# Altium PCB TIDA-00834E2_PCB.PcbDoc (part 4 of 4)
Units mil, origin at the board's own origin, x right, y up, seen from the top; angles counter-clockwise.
Board outline 7480.31 x 4133.86 mil, 4 copper layers (Top Layer, GND, PWR, Bottom Layer), stack 61.912 mil thick; 550 components, 248 nets, 1167 pads, 312 vias.
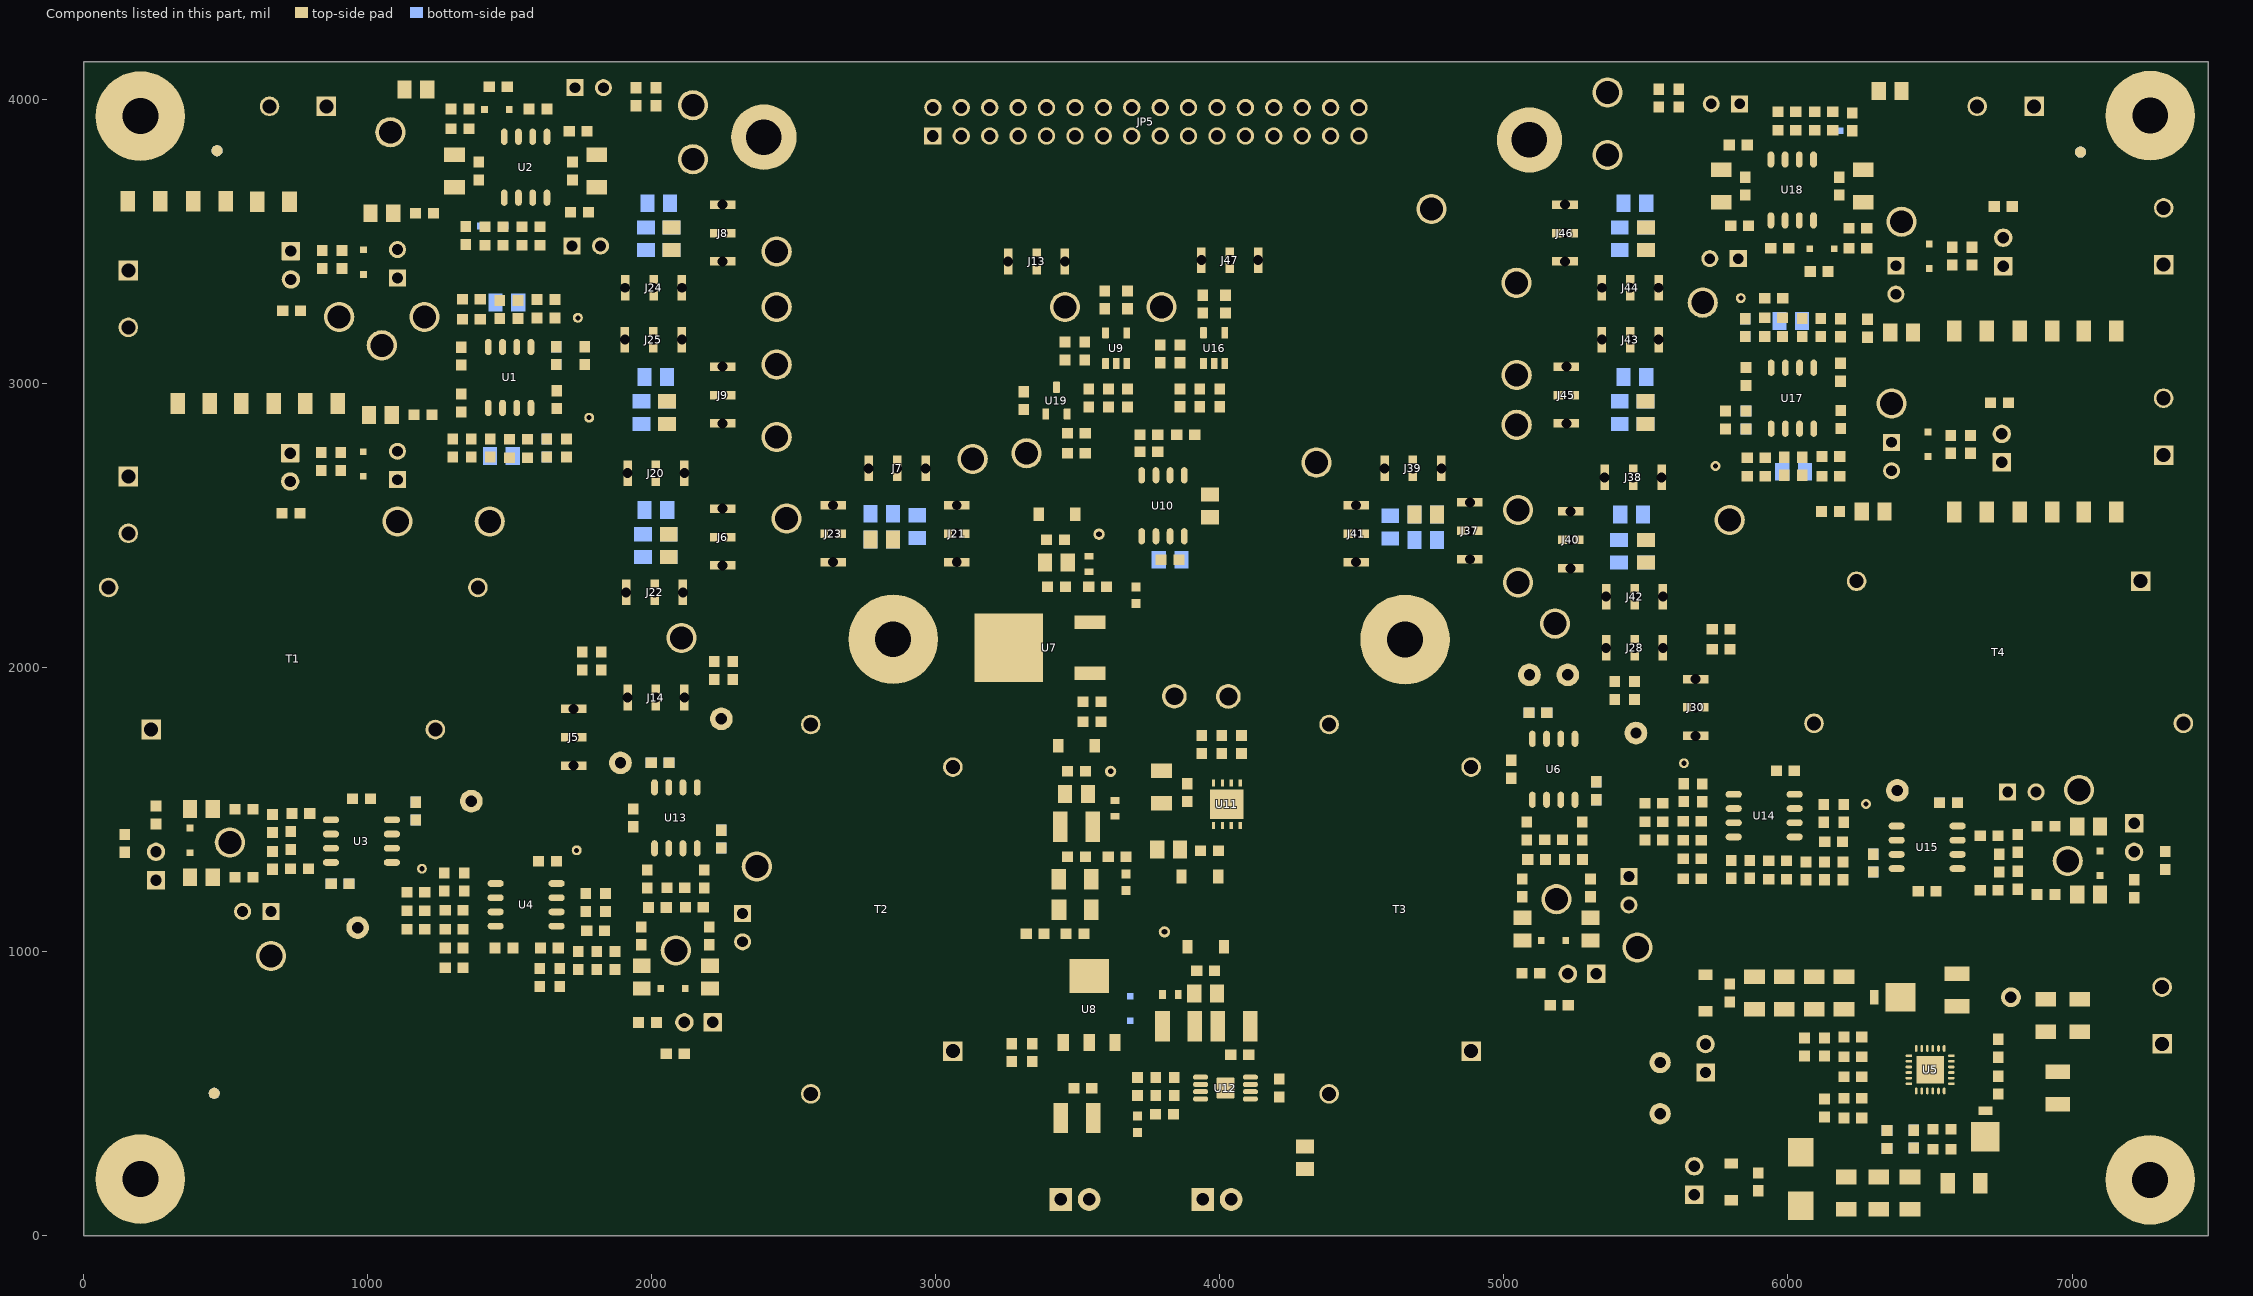
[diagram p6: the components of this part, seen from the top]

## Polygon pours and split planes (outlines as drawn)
GND1 on Top Layer "GND1_L01_P068" (solid, remove dead copper, pour order 68): 5750,135 5760,145 5825,145 5845,145 5855,155 5855,165 5865,175 5935,175 5975,175 5995,155 6065,155 6115,155 6130,140 6155,115 6180,115 6580,115 6590,105 6590,75 6590,55 6565,30 6430,30 5775,30 5750,55
NetC25_1 on Top Layer "Top Layer-No Net" (solid, remove dead copper, pour order 32): 5585,295 5585,240 5615,210 5680,210 5715,210 5745,240 5805,240 5845,240 5855,230 5855,225 5855,210 5860,205 5865,200 5890,200 5925,200 5935,210 5935,235 5945,245 6100,245 6120,245 6135,230 6135,215 6135,190 6145,180 6195,180 6495,180 6505,170 6505,145 6512.64,137.36 6582.36,137.36 6590,145 6590,240 6580,250 6540,250 6530,260 6530,320 6525,325 6430,325 6425,320 6425,260 6415,250 6225,250 6210,265 6210,305 6210,335 6195,350 6193.86,351.14 6116.85,351.14 5616.14,351.14 5585,320
NetD4_2 on Top Layer "Top Layer-No Net" (solid, remove dead copper, pour order 26): 6540,511 6540,450 6555,435 6625,435 6630,435 6635,430 6640,425 6670,425 6770,425 6795,400 6795,345 6805,335 7035,335 7045,345 7045,465 7045,475 7035,485 7030,490 6910,490 6820,490 6790,460 6685,460 6680,460 6655,485 6655,520 6655,525 6645,535 6640,540 6590,540 6569,540
GND1 on Top Layer "Top Layer-No Net" (solid, remove dead copper, pour order 16): 5635,925 5635,909 5644,900 5737,900 5740,900 5770,870 5814,870 5825,870 5840,885 5843,888 6117,888 6228,888 6235,895 6235,975 6230,980 5648,980 5635,967 5635,926
NetD7_1 on Top Layer "Top Layer-No Net" (solid, remove dead copper, pour order 18): 6345,975 6345,775 6390,730 6390,625 6405,610 6435,610 6440,615 6440,645 6430,655 6430,725 6475,770 6675,770 6695,790 6695,815 6675,835 6495,835 6480,850 6480,975 6475,980 6350,980
NetD4_1 on Top Layer "Top Layer-No Net" (solid, remove dead copper, pour order 24): 6640,400 6625,385 6625,265 6650,240 6650,115 6660,105 6755,105 6765,115 6765,390 6755,400
+5V_IN on Top Layer "Top Layer-No Net" (solid, remove dead copper, pour order 6): 6565,610 6565,685 6600,720 6785,720 6810,745 7395,745 7410,730 7410,570 7390,550 6805,550 6790,565 6790,665 6780,675 6625,675 6615,665 6615,610
GND1 on Top Layer "Top Layer-No Net" (solid, remove dead copper, pour order 28): 6805,895 6550,895 6530,915 6530,965 6545,980 7380,980 7410,950 7410,830 7390,810 6890,810 6885,810 6870,825 6870,875 6850,895
NetC35_1 on Top Layer "Top Layer-No Net" (solid, remove dead copper, pour order 20): 5635,800 5645,810 5750,810 5760,820 5760,835 5770,845 5830,845 5850,825 6240,825 6260,845 6260,975 6265,980 6315,980 6320,975 6320,765 6370,715 6370,625 6370,605 6360,595 6325,595 6305,615 6305,725 6275,755 6090,755 6080,745 6080,690 6070,680 5995,680 5985,690 5985,745 5975,755 5795,755 5775,735 5775,650 5765,640 5645,640 5635,650
AGND on Top Layer "Top Layer-No Net" (solid, remove dead copper, pour order 34): 3817.28,441.64 3822.28,446.64 3982.24,446.64 3990,454.4 3990,590 3978.36,601.64 3897.28,601.64 3887.28,611.64 3887.28,780.9 3898.02,791.64 3957.28,791.64 3962.28,796.64 3962.28,961.64 3997.28,996.64 3997.28,1091.64 4007.28,1101.64 4068.36,1101.64 4080,1090 4080,855 4022.28,797.28 4022.28,686.64 4050,658.92 4050,394.36 4037.28,381.64 3828.36,381.64 3817.28,392.72
-12V on Top Layer "Top Layer-No Net" (solid, remove dead copper, pour order 36): 3882,883 3780,985 3780,1095 3790,1105 3885,1105 3895,1105 3905,1095 3905,1065 3905,985 3935,955 3935,920 3935,830 3925,820 3891,820 3882,829
-14V on Top Layer "Top Layer-No Net" (solid, remove dead copper, pour order 38): 4080,795 4090,805 4175,805 4185,795 4185,620 4170,605 4095,605 4080,620
+14V on Top Layer "Top Layer-No Net" (solid, remove dead copper, pour order 40): 3527.91,545 3537.91,555 3620,555 3630,545 3630,325 3620,315 3540,315 3527.91,327.09
AGND on Top Layer "Top Layer-No Net" (solid, remove dead copper, pour order 42): 3250,535 3250,620 3260,630 3360,630 3368.54,621.46 3368.54,556.46 3390,535 3467.91,535 3497.91,535 3502.91,530 3502.91,505 3502.91,485 3492.91,475 3462.91,445 3462.91,420 3462.91,355 3452.91,345 3397.91,345 3260,345 3250,355 3250,525
AGND on Top Layer "Top Layer-No Net" (solid, remove dead copper, pour order 44): 3325,1750 3435,1750 3450.53,1734.47 3450.53,1675 3455.53,1670 3479.07,1670 3485.53,1663.54 3485.53,1513.15 3465.53,1493.15 3465.53,1380 3485.53,1360 3485.53,1325 3475.53,1315 3322.62,1315 3312.62,1325 3312.62,1737.62
NetC54_1 on Top Layer "Top Layer-No Net" (solid, remove dead copper, pour order 46): 3615,850 3480,850 3470,860 3470,980 3505.53,1015.53 3505.53,1375 3525.53,1395 3525.53,1470 3525.53,1483.15 3535.53,1493.15 3562.46,1493.15 3592.38,1493.15 3600.53,1485 3600.53,1465 3600.53,1390 3620.53,1370 3625.53,1365 3625.53,1310 3625.53,860.53
NetC54_2 on Top Layer "Top Layer-No Net" (solid, remove dead copper, pour order 48): 3459.53,1291 3475.53,1275 3475.53,1110 3480.53,1105 3480.53,1032.53 3473,1025 3364,1025 3355.53,1033.47 3355.53,1275 3371.53,1291
+12V on Top Layer "Top Layer-No Net" (solid, remove dead copper, pour order 50): 3542.62,1750 3650,1750 3657.62,1742.38 3657.62,1600 3647.62,1590 3600.53,1590 3590.53,1580 3590.53,1570 3590.53,1530 3580.53,1520 3550.53,1520 3520.53,1520 3510.53,1530 3510.53,1660 3510.53,1665 3540.53,1695 3540.53,1747.91
AGND on Top Layer "Top Layer-No Net" (solid, remove dead copper, pour order 54): 3375,2605 3375,2500 3385,2490 3410,2490 3415,2485 3415,2210 3375,2170 3375,1950 3140,1950 3140,2210 3250,2320 3250,2605 3260,2615 3365,2615
+3.3V on Top Layer "Top Layer-No Net" (solid, remove dead copper, pour order 56): 3535,2605 3535,2510 3490,2465 3490,2340 3485,2335 3440,2335 3435,2340 3435,2495 3475,2535 3475,2605 3485,2615 3525,2615
AGND on Top Layer "Top Layer-No Net" (solid, remove dead copper, pour order 58): 3755,1545 3930,1545 3955,1570 4104.65,1570 4115,1559.65 4115,1480.35 4104.65,1470 3925,1470 3895,1440 3820,1440 3805,1425 3805,1305 3790,1290 3755,1290 3740,1305 3740,1530
NetC49_1 on Top Layer "NETC49_1_L01_P076" (solid, remove dead copper, pour order 76): 3525,2345 3525,2320 3525,2315 3520,2310 3515,2305 3460,2305 3445,2305 3440,2300 3440,2270 3440,2160 3465,2135 3540,2135 3585,2135 3610,2160 3610,2195 3575,2230 3560,2245 3555,2250 3555,2320 3555,2345 3550,2350 3530,2350
AGND on GND "AGND_L02_P066" (solid, remove dead copper, pour order 66): 50,3700 75,3725 225,3725 400,3725 425,3750 425,3950 425,4075 450,4100 1125,4100 1150,4075 1150,3400 1194,3356 1836,3356 1950,3470 1950,3475 1950,3775 2000,3825 2100,3925 2100,3975 2100,4075 2125,4100 2250,4100 5400,4100 5425,4075 5425,3900 5500,3825 5575,3750 5575,3725 5575,3475 5700,3350 6300,3350 6375,3425 6375,3550 6375,4075 6400,4100 7025,4100 7050,4075 7050,4025 7050,3750 7075,3725 7150,3725 7400,3725 7425,3700 7425,1025 7400,1000 7175,1000 5605,1000 5525,920 5525,775 5425,675 5150,400 5025,275 3375,275 3350,250 3350,75 3325,50 550,50 450,50 425,75 425,250 425,375 400,400 75,400 50,425
GND2 on GND "GND2_L02_P064" (solid, remove dead copper, pour order 64): 6350,4090 6325,4115 6075,4115 5480,4115 5470,4115 5450,4095 5450,4055 5450,3935 5600,3785 5600,3595 5600,3495 5720,3375 6275,3375 6350,3450
GND on GND "GND_L02_P062" (solid, remove dead copper, pour order 62): 1185,4085 1200,4100 1450,4100 2045,4100 2055,4100 2075,4080 2075,4040 2075,3935 1925,3785 1925,3580 1925,3505 1805,3385 1220,3385 1185,3420
GND1 on GND "GND1_L02_P060" (solid, remove dead copper, pour order 60): 7405,980 5635,980 5550,895 5550,850 5550,750 5050,250 3405.75,250 3375,219.25 3375,75 3420,30 5015,30 7030,30 7050,50 7050,140 7050,400 7075,425 7405,425 7410,425 7435,450 7435,910 7435,950
-12V on Bottom Layer "-12V_L04_P074" (solid, remove dead copper, pour order 74): 5285,1550 5290,1555 5345,1555 5365,1555 5405,1595 5415,1605 5435,1605 5515,1605 5715,1405 5815,1305 5815,1195 5815,1185 5830,1170 5835,1165 5880,1165 5940,1225 6135,1420 6280,1420 6520,1420 6575,1475 6580,1480 6580,1535 6580,1580 6590,1590 6870,1590 6940,1520 6940,115 6900,75 5935,75 5730,280 3420,280 3215,75 845,75 775,145 775,1140 850,1215 850,1230 850,1250 855,1255 885,1255 890,1250 890,1215 905,1200 905,1045 925,1025 1075,1025 1175,1025 1450,1300 1450,2090 1660,2300 1705,2300 1725,2280 1725,2235 1725,2070 1660,2005 1660,1145 1545,1030 1545,905 1555,895 1614.28,895 1699.74,980.46 1699.74,1139.74 1760,1200 1945,1200 1957.74,1212.74 2130,1385 2285,1385 2300,1370 2300,1205 2260,1165 2260,945 2195,880 2075,760 2075,510 2135,450 2260,450 3245,1435 3910,1435 4765,580 5305,580 5450,725 5450,890 5495,935 5495,1515 5460,1550 5445,1550 5410,1515 5360,1515 5290,1515 5285,1520
+12V on PWR "+12V_L03_P070" (solid, remove dead copper, pour order 70): 100,3650 125,3675 450,3675 475,3700 475,4025 500,4050 1050,4050 1075,4075 1575,4075 1600,4075 1625,4050 1625,4025 1625,3975 1650,3950 1875,3950 2100,3950 2125,3975 2125,4000 2150,4025 2275,4025 5425,4025 5475,4075 5800,4075 6450,4075 6500,4025 6750,4025 6975,4025 7000,4000 7000,3950 7000,3700 7025,3675 7100,3675 7350,3675 7375,3650 7375,3025 7375,1075 7350,1050 5575,1050 5475,950 5475,800 5000,325 3350,325 3300,275 3300,125 3275,100 525,100 500,125 500,325 500,450 475,475 325,475 125,475 100,500

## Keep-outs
Keep-Out Layer:
  lines w10: 25,375 400,375 400,0 ; 25,3741.85 400,3741.85 400,4107.01 ; 7075,21.85 7075,396.85 7450,396.85 ; 7075,4108.86 7075,3743.7 7450,3743.7 ; 25,25 25,4108.86 7455.31,4108.86 7455.31,25 25,25
  text ".Layer_Name" at 577,-858.49 h60

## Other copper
Top Layer:
  region net +5V_IN: 6465,705 6465,650 6470,645 6530,645 6535,650 6535,705 6530,710 6470,710
  text ".Layer_Name" at 577,-858.49 h60
GND:
  pour cut-out: 2250,4000 2250,3725 2550,3725 2550,4000
  pour cut-out: 4940,3995 4940,3720 5240,3720 5240,3995
  pour cut-out: 2655,2290 2655,1915 3055,1915 3055,2290
  pour cut-out: 4457,2289 4457,1914 4857,1914 4857,2289
  text ".Layer_Name" at 577,-858.49 h60
PWR:
  pour cut-out: 4940,2435 4940,2381.77 4940.08,2381.7 4938.38,2380 4840,2380 4840,2435
  pour cut-out: 5850,115 5850,40 5975,40 5975,70 5975,100 5930,115
  pour cut-out: 2250,4000 2250,3725 2550,3725 2550,4000
  pour cut-out: 4940,3995 4940,3720 5240,3720 5240,3995
  pour cut-out: 2655,2290 2655,1915 3055,1915 3055,2290
  pour cut-out: 4457,2289 4457,1914 4857,1914 4857,2289
  text ".Layer_Name" at 577,-858.49 h60
Bottom Layer:
  pour cut-out: 3657,873.5 3656.51,873.01 3656.51,717.51 3717,717.51 3717,873.5
  text ".Layer_Name" at 577,-858.49 h60

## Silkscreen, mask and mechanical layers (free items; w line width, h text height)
Top Overlay:
  circle w10: c3448,609 r9
  circle w6: c3885,575 r5.66
  circle w6: c3719.34,2415 r5.66
  circle w6: c3919.34,3035 r5.66
  circle w6: c6609.34,530 r5.66
  circle w6: c6609.34,1250 r5.66
  circle w6: c5759.34,1570 r5.66
  circle w6: c5059.34,1520 r5.66
  circle w6: c5934.34,2795 r5.66
  circle w6: c5924.34,3530 r5.66
  circle w6: c1964.34,1355 r5.66
  circle w6: c1405.42,1252.32 r5.66
  circle w6: c859.34,1510 r5.66
  circle w6: c1574.34,3180 r5.66
  circle w6: c1639.34,3915 r5.66
  circle w6: c3594.34,3030 r5.66
  circle w20: c2365,3629 r22
  circle w20: c2206,3334 r22
  circle w20: c2205,3195 r22
  circle w20: c2286,3157 r22
  circle w20: c2210,2683 r22
  circle w20: c2291,2656 r22
  circle w20: c2212,2254 r22
  circle w20: c1610,1857 r22
  circle w20: c2114,1800 r22
  circle w20: c2642,2679 r22
  circle w20: c2963,2826 r22
  circle w20: c3190,2573 r22
  circle w20: c3457,3536 r22
  circle w20: c3934,3535 r22
  circle w20: c4363,2571 r22
  circle w20: c4877,2273 r22
  circle w20: c4783,2810 r22
  circle w20: c5256,2700 r22
  circle w20: c5205,2637 r22
  circle w20: c5187,3150 r22
  circle w20: c5258,3199 r22
  circle w20: c5258,3321 r22
  circle w20: c5096,3632 r22
  circle w20: c5258,2244 r22
  circle w20: c5257,2070 r22
  circle w20: c5785,1961 r22
  lines w6: 497,1451 497,1556 ; 1245,640 1245,888 ; 1300,3415 1300,3342 ; 1560,670 1560,820 ; 1866,1360 1866,1253 ; 2060,816 2080,816 2084,820 2084,833 ; 2219,1156 2228,1156 2260,1188 ; 2297,961 2252,1006 2238,1006 ; 3564,2868 3545,2868 3540,2873 3540,2888 ; 3957.27,2890.02 3957.27,2888.73 3971,2875 4004,2875 4016,2863 ; 4075,3210 4154,3210 ; 5580,1040 5580,1218 ; 5755,2793 5762,2800 5762,2785 5754,2793 5825,2793 5834,2802 ; 5868,3329 5875,3322 5860,3322 5868,3330 5868,3282 5884,3266 ; 5899,1123 5899,1206 ; 6306.11,3573.88 6306.11,3575.11 6325,3594 6325,3620 6345,3640 6345,3659 ; 6940,1480 6940,1621 ; 1245,888 1239,882 1251,882 1245,888 ; 1300,3342 1293,3349 1306,3349 1306,3348 1300,3342 ; 1560,820 1553,813 1567,813 1560,820 ; 1866,1253 1860,1259 1871,1259 1871,1258 1866,1253 ; 2084,833 2079,828 2089,828 2084,833 ; 2238,1006 2244,1012 2244,1000 2238,1006 ; 2260,1188 2251,1188 2260,1179 2260,1188 ; 3540,2888 3533,2881 3546,2881 3546,2882 3540,2888 ; 5580,1218 5574,1212 5586,1212 5580,1218 ; 5899,1206 5893,1200 5904,1200 5904,1201 5899,1206 ; 6940,1621 6934,1615 6946,1615 6940,1621 ; 3395,635 3395,885 3455,885 3455,990 3625,990 3625,885 3685,885 3685,635 3395,635 ; 4074.5,3209.5 4082,3217 4082,3202 4074.5,3209.5
  text "2" at 2971,4045 h60
  text "14" at 3546,4045 h60
  text "20" at 3846,4045 h60
  text "8" at 3266,4040 h60
  text "26" at 4141,4040 h60
  text "32" at 4436,4040 h60
  text "19" at 3838.4,3750 h60
  text "7" at 3281,3745 h60
  text "13" at 3556,3745 h60
  text "25" at 4146,3745 h60
  text "31" at 4441,3745 h60
  text "1" at 2976,3740 h60
  text "FID1" at 435,415 h30
  text "'.PRJ_Number'.PCB_Rev" at 1694,149 h108.27
  text ".Layer_Name" at 577,-858.49 h60
Bottom Overlay:
  text "2" at 2991,4045 h60
  text "14" at 3636,4045 h60
  text "20" at 3946,4045 h60
  text "8" at 3326,4040 h60
  text "26" at 4241,4040 h60
  text "32" at 4536,4040 h60
  text "19" at 3931,3755 h60
  text "7" at 3301,3745 h60
  text "13" at 3656,3745 h60
  text "25" at 4241,3745 h60
  text "31" at 4521,3745 h60
  text "1" at 2996,3740 h60
  text "FID2" at 415,3695 h72.83
  text "FID3" at 6970,3665 h72.83
  text ".Layer_Name" at 577,-858.49 h60
Top Paste:
  text ".Layer_Name" at 577,-858.49 h60
Bottom Paste:
  text ".Layer_Name" at 577,-858.49 h60
Top Solder:
  text ".Layer_Name" at 577,-858.49 h60
  text ".Layer_Name" at 577,-858.49 h60
Bottom Solder:
  text ".Layer_Name" at 577,-858.49 h60
Drill Guide:
  text ".Layer_Name" at 577,-858.49 h60
M1 Board Outline:
  the board outline again, w10
M2 Board Dimensions:
  rectangle: 0,-275 125,-150
  rectangle: 125,-400 500,-275
  lines w7: 0,-275 1000,-275 ; 125,-400 125,-150 ; 250,-400 250,-150 ; 500,-400 500,-150 ; 750,-400 750,-150 ; 0,-400 1000,-400 1000,-150 0,-150 0,-400
M3 3D STEP Top:
  text ".Layer_Name" at 577,-858.49 h60
M4 3D STEP Bottom:
  text ".Layer_Name" at 577,-858.49 h60
M5 Assembly Top:
  circle w6: c3598,3051 r7.07
  circle w6: c3943,3052 r7.07
  circle w6: c3440,650 r7.07
  circle w6: c3975,1445 r7.07
  circle w6: c3388,2870 r7.07
  lines w4: 3955,1425 4095,1425 4095,1615 3965,1615 3955,1615 3955,1425
  lines w10: -292,-930.17 6308,-930.17 ; -292,-726.83 6310,-726.83 ; -292,-523.5 -292,-1133.5 3713,-1133.5 6310,-1133.5 6310,-523.5 -291.5,-523.5 -291.5,-1133.5 1284,-1133.5 ; 2173,-1133.5 2173,-523.5 ; 3440,-726.83 3440,-523.5 ; 4280,-726.83 4280,-523.5 ; 4902,-1140 4902,-937.17
  text "COMPONENTS MARKED 'DNP' SHOULD NOT BE POPULATED." at 1153.5,-318.5 h60
  text "ASSEMBLY VARIANT:" at 1153,-434 h60
  text ".VariantName" at 2189,-434 h60
  text "PCB VIEWED FROM TOP SIDE" at -228.5,-655.67 h60
  text "BOARD #:" at 2248,-655.67 h60
  text ".PRJ_Number" at 2793.5,-655.67 h60
  text "REV:" at 3638,-655.67 h60
  text ".PCB_Rev" at 3929.5,-655.67 h60
  text "SVN REV:" at 4476,-655.67 h60
  text ".VersionControl_RevNumber" at 4982,-655.67 h60
  text ".Layer_Name" at 577,-858.49 h60
  text "TID #:" at 2248,-859 h60
  text ".TID" at 2793.5,-859 h60
  text "PLOT NAME =" at -228.5,-1064.34 h60
  text ".plot_File_Name" at 577,-1064.34 h60
  text "GENERATED    :" at 2250,-1064.34 h60
  text ".Print_Date" at 3119.5,-1064.34 h60
  text ".Print_Time" at 3848.5,-1064.34 h60
  text "TEXAS INSTRUMENTS" at 5113,-1064.34 h60
M6 Assembly Bottom:
  circle w6: c2975,3800 r10
  lines w10: -292.5,-727.33 6309.5,-727.33 ; -290.5,-930.67 6309.5,-930.67 ; 1115.5,-1140.5 1115.5,-937.67 ; 1737.5,-727.33 1737.5,-524 ; 2577.5,-727.33 2577.5,-524 ; 3844.5,-1134 3844.5,-524 ; 4733.5,-1134 6309,-1134 6309,-524 -292.5,-524 -292.5,-1134 2304.5,-1134 6309.5,-1134 6309.5,-524
  text "COMPONENTS MARKED 'DNP' SHOULD NOT BE POPULATED." at 6102,-318 h60
  text ".VariantName" at 5058,-434 h60
  text "ASSEMBLY VARIANT:" at 6097,-434 h60
  text ".VersionControl_RevNumber" at 1035.5,-656.17 h60
  text "SVN REV:" at 1541.5,-656.17 h60
  text ".PCB_Rev" at 2088,-656.17 h60
  text "REV:" at 2379.5,-656.17 h60
  text ".PRJ_Number" at 3224,-656.17 h60
  text "BOARD #:" at 3769.5,-656.17 h60
  text "PCB VIEWED FROM BOTTOM SIDE" at 6246,-656.17 h60
  text ".Layer_Name" at 5805,-840 h60
  text ".TID" at 3224,-859.5 h60
  text "TID #:" at 3769.5,-859.5 h60
  text "TEXAS INSTRUMENTS" at 904.5,-1064.84 h60
  text ".Print_Time" at 2169,-1064.84 h60
  text ".Print_Date" at 2898,-1064.84 h60
  text "GENERATED    :" at 3767.5,-1064.84 h60
  text ".plot_File_Name" at 5440.5,-1064.84 h60
  text "PLOT NAME =" at 6246,-1064.84 h60
M9 Title Sheet:
  drawing of 57 lines, arcs and shapes, not listed
  text "1" at 739.84,8036.5 h70
  text "2" at 3235.5,8036.5 h70
  text "3" at 5724.84,8036.5 h70
  text "4" at 8231.51,8036.5 h70
  text "5" at 10730.5,8036.5 h70
  text "6" at 13235.5,8036.5 h70
  text "A" at -416.5,6893.5 h70
  text "A" at 14383.5,6893.5 h70
  text "B" at -416.5,4513.5 h70
  text "B" at 14383.5,4513.5 h70
  text "C" at -416.5,2138.5 h70
  text "C" at 14383.5,2138.5 h70
  text "PROJECT TITLE:" at 11343.5,277.5 h45
  text ".PRJ_Title" at 11393.5,144.17 h70
  text "DESIGNED FOR:" at 11343.5,-23.5 h45
  text ".PRJ_Customer" at 11393.5,-163.5 h70
  text "D" at -416.5,-231.5 h70
  text "D" at 14383.5,-231.5 h70
  text "FILE NAME:" at 11343.5,-323.5 h45
  text ".PCB_File_Name_No_Path" at 11393.5,-443.5 h70
  text "Texas Instruments (TI) and/or its licensors do not warrant the accuracy or completeness of this specification" at 6374,-605.34 h45
  text "ENGINEER:" at 11343.5,-613.5 h45
  text "LAYOUT BY:" at 12848.5,-613.5 h45
  text "or any information contained therein. TI and/or its licensors do not warrant that this design will meet" at 6329.01,-718 h45
  text ".PRJ_Engineer" at 11393.5,-768.49 h70
  text ".PCB_Layout" at 12899,-768.49 h70
  text "the specifications, will be suitable for your application or fit for any particular purpose, or will operate in" at 6329.01,-830.67 h45
  text "ALTIUM DESIGNER VERSION:" at 12848.5,-923.5 h45
  text "an implementation. TI and/or its licensors do not warrant that the design is production worthy. You should" at 6329.01,-943.33 h45
  text "completely validate and test your design implementation to confirm the system functionality for your application." at 6374,-1056 h45
  text ".print_Scale" at 11393.5,-1056.83 h70
  text ".Application_BuildNumber" at 12899,-1056.83 h70
  text "1" at 739.84,-1263.5 h70
  text "2" at 3235.5,-1263.5 h70
  text "3" at 5724.84,-1263.5 h70
  text "4" at 8231.51,-1263.5 h70
  text "5" at 10730.5,-1263.5 h70
  text "6" at 13235.5,-1263.5 h70
M10 Fab Notes:
  drawing of 189 lines, arcs and shapes, not listed
  text "DESIGN INFORMATION" at 12378.02,6201 h60
  text "MIN. TRACK WIDTH:" at 11733.46,6021 h60
  text "8" at 12829.7,6021 h60
  text "MIL" at 13068,6020 h60
  text "MIL" at 13070,5891 h60
  text "MIN. CLEARANCE:" at 11733.46,5889 h60
  text "7.874" at 12769.7,5889 h60
  text "MIN. VIA PAD SIZE:" at 11733.46,5757 h60
  text "19.685" at 12675,5745 h60
  text "MIL" at 13073,5745 h60
  text "0.15mm (5.906MIL)" at 12428.46,5615.29 h60
  text "EXTERNAL" at 13242,5613 h60
  text "MINIMUM ANNULAR RING" at 11404.23,5611 h60
  text "PER" at 11604.23,5493 h60
  text "IPC-D-275 CLASS 2 LEVEL C" at 11824.23,5493 h60
  text "MIL, HOLES" at 13312.46,5380.71 h60
  text "+/-" at 12920,5380 h60
  text "+/-" at 13774,5380 h60
  text "REGISTRATION TOLERANCES:" at 11404.23,5375 h60
  text "METAL" at 12604,5375 h60
  text "5" at 13180.2,5375 h60
  text "3" at 14013.2,5375 h60
  text "MIL" at 14129.46,5375 h60
  text "+/-" at 13774,5262 h60
  text "HOLE SIZE TOLERANCE (UNLESS OTHERWISE SPECIFIED):" at 11404.23,5257 h60
  text "3" at 14013.2,5257 h60
  text "MIL" at 14129.46,5257 h60
  text "MATERIAL:" at 11329.46,5047.54 h60
  text "FR-4 High Tg" at 12315.9,4907.21 h60
  text "FR-408" at 11750.46,4898.64 h60
  text "OTHER" at 13238.46,4898.64 h60
  text "X" at 12161,4895 h60
  text "62 MIL (1.6mm) +/-10%" at 12070.56,4735.92 h60
  text "THICKNESS:" at 11404.23,4731.64 h60
  text "X" at 11942.4,4731.64 h60
  text "OTHER" at 13355.46,4731.64 h60
  text "TOLERANCE:" at 11404.23,4573.64 h60
  text "X" at 12243.53,4573.64 h60
  text "ANSI IPC-6012 TYPE 3 CLASS 2" at 12430.48,4573.64 h60
  text "OTHER +/-" at 12430.46,4417.64 h60
  text "BOW & TWIST:" at 11404.23,4260.64 h60
  text "X" at 12243.53,4260.64 h60
  text "ANSI IPC-6012 TYPE 3 CLASS 2" at 12430.48,4260.64 h60
  text "OTHER +/-" at 12430.46,4102.13 h60
  text "DRILLING:" at 11329.46,3963.64 h60
  text "REFERENCE:" at 11404.23,3846.64 h60
  text "X" at 12052.46,3846.64 h60
  text "AS SHOWN" at 12239.46,3846.64 h60
  text "X" at 12953.46,3846.64 h60
  text "NC_DRILL FILES" at 13090.46,3846.64 h60
  text "PTH COPPER THICKNESS:" at 11404.23,3688.64 h60
  text "X" at 12534.46,3688.64 h60
  text "20-30 um" at 12671.46,3688.64 h60
  text "OTHER" at 13388.46,3688.64 h60
  text "BOARD FINISH:" at 11329.46,3529.64 h60
  text "SILKSCREEN:" at 11484.68,3411.64 h60
  text "X" at 12433.46,3411.64 h60
  text "TOP" at 12559.46,3411.64 h60
  text "X" at 12943.46,3411.64 h60
  text "BOTTOM" at 13070.46,3411.64 h60
  text "SILKSCREEN COLOR:" at 11484.68,3244.64 h60
  text "X" at 12432.42,3244.64 h60
  text "WHITE" at 12559.46,3244.64 h60
  text "OTHER" at 13070.46,3244.64 h60
  text "X" at 12563.42,3085.44 h60
  text "GREEN" at 12690.46,3085.44 h60
  text "OTHER" at 13308.46,3085.44 h60
  text "SOLDER RESIST COLOR:" at 11484.68,3074.64 h60
  text "X" at 12563.42,2915.44 h60
  text "MATTE" at 12690.46,2915.44 h60
  text "SEMI-GLOSS" at 13308,2914.8 h60
  text "IMMERSION GOLD (ENIG)" at 12390.46,2726.92 h60
  text "ENEPIG" at 13728,2723.64 h60
  text "SURFACE FINISH:" at 11329.46,2722.64 h60
  text "X" at 12203.51,2722.64 h60
  text "IMM. TIN/SILVER OR EQUIV" at 11659,2565.64 h60
  text "OTHER" at 13090.46,2565.64 h60
  text "ARRAY/PANEL:" at 11329.46,2386.64 h60
  text "CUT AND TRIM PER M1 BOARD OUTLINE" at 12390.46,2382.35 h60
  text "N.C. ROUTE" at 12390.46,2230.64 h60
  text "X" at 13069.46,2230.64 h60
  text "V. SCORE" at 13256.46,2230.64 h60
  text "CERTIFICATION:" at 11329.46,2093.64 h60
  text "MATERIALS AND WORKMANSHIP FOR ALL PCBS" at 12054.46,2093.64 h60
  text "TO MEET OR EXCEED THE REQUIREMENTS OF:" at 12054.46,1995.64 h60
  text "X" at 11680.96,1859.13 h60
  text "ANSI IPC-A-600F CLASS ->" at 11819.96,1859.13 h60
  text "X" at 13459.02,1859.13 h60
  text "2" at 13577.96,1859.14 h60
  text "1" at 13262.96,1857.64 h60
  text "3" at 13931.96,1857.64 h60
  text "X" at 12495.02,1699.64 h60
  text "RoHS" at 12631.96,1699.64 h60
  text "OTHER" at 13276.36,1699.64 h60
  text "PER ORDER" at 13673.42,1699.64 h60
  text "ALL BOARDS MUST MEET OR EXCEED UL94-V0 REQUIREMENTS." at 11357,1534 h60
  text "PCB MUST BEAR THE UL94V-0 UL REGISTERED MATERIAL ID NUMBER" at 11357,1414 h60
  text "VIA TENTING:" at 12546,1274 h60
  text "X" at 13306,1272 h60
  text "YES" at 13095.67,1264.92 h60
  text "NO" at 13460.47,1259.69 h60
  text "ADDITIONAL REQUIREMENTS:" at 11329.46,1240.64 h60
  text "IMPEDANCE CONTROL:" at 12568,1145 h60
  text "YES" at 13552,1144 h60
  text "X" at 14094,1137 h60
  text "NO" at 13927.47,1126.69 h60
  text "MICROSECTION:" at 11404.23,1125.64 h60
  text "YES" at 12309.96,1125.64 h60
  text "REQUIRED" at 13171.46,969.49 h60
  text "BARE BOARD ELEC. TEST:" at 11404.23,966.64 h60
  text "NONE" at 12709.96,966.64 h60
  text "X" at 13044.46,966.64 h60
  text "PER ORDER" at 13763.46,966.64 h60
M11 Gerber Information:
  lines w10: -292,-930.17 6308,-930.17 ; -292,-726.83 6310,-726.83 ; -292,-523.5 -292,-1133.5 3713,-1133.5 6310,-1133.5 6310,-523.5 -291.5,-523.5 -291.5,-1133.5 1284,-1133.5 ; 2173,-1133.5 2173,-523.5 ; 3440,-726.83 3440,-523.5 ; 4280,-726.83 4280,-523.5 ; 4902,-1140 4902,-937.17
  text "ALL ARTWORK VIEWED FROM TOP SIDE" at -228.5,-655.67 h60
  text "BOARD #:" at 2248,-655.67 h60
  text ".PRJ_Number" at 2793.5,-655.67 h60
  text "REV:" at 3638,-655.67 h60
  text ".PCB_Rev" at 3929.5,-655.67 h60
  text "SVN REV:" at 4476,-655.67 h60
  text ".VersionControl_RevNumber" at 4982,-655.67 h60
  text "LAYER NAME =" at -228.5,-858.49 h60
  text "TID #:" at 2248,-859 h60
  text ".TID" at 2793.5,-859 h60
  text "PLOT NAME =" at -228.5,-1064.34 h60
  text ".plot_File_Name" at 577,-1064.34 h60
  text "GENERATED    :" at 2250,-1064.34 h60
  text ".Print_Date" at 3119.5,-1064.34 h60
  text ".Print_Time" at 3848.5,-1064.34 h60
  text "TEXAS INSTRUMENTS" at 5113,-1064.34 h60
M12 Stackup:
  drawing of 295 lines, arcs and shapes, not listed
  text "Layer" at 9815.58,7870 h60
  text "Name" at 10225.49,7870 h60
  text "Material" at 11155.23,7870 h60
  text "Thickness" at 12015,7870 h60
  text "Constant" at 12664.84,7870 h60
  text "Board Layer Stack" at 13234.7,7870 h60
  text "1" at 9815.58,7750 h60
  text "Top Overlay" at 10225.49,7750 h60
  text "2" at 9815.58,7630 h60
  text "Top Solder" at 10225.49,7630 h60
  text "Solder Resist" at 11155.23,7630 h60
  text "0.40mil" at 12015,7630 h60
  text "4.3" at 12664.84,7630 h60
  text "3" at 9815.58,7510 h60
  text "Top Layer" at 10225.49,7510 h60
  text "Copper" at 11155.23,7510 h60
  text "1.38mil" at 12015,7510 h60
  text "4" at 9815.58,7390 h60
  text "Dielectric1" at 10225.49,7390 h60
  text "FR-4 High Tg" at 11155.23,7390 h60
  text "6.70mil" at 12015,7390 h60
  text "4.3" at 12664.84,7390 h60
  text "5" at 9815.58,7270 h60
  text "GND" at 10225.49,7270 h60
  text "Copper" at 11155.23,7270 h60
  text "1.38mil" at 12015,7270 h60
  text "6" at 9815.58,7150 h60
  text "Dielectric 2" at 10225.49,7150 h60
  text "FR-4 High Tg" at 11155.23,7150 h60
  text "43.00mil" at 12015,7150 h60
  text "4.3" at 12664.84,7150 h60
  text "7" at 9815.58,7030 h60
  text "PWR" at 10225.49,7030 h60
  text "Copper" at 11155.23,7030 h60
  text "1.38mil" at 12015,7030 h60
  text "8" at 9815.58,6910 h60
  text "Dielectric 3" at 10225.49,6910 h60
  text "FR-4 High Tg" at 11155.23,6910 h60
  text "6.70mil" at 12015,6910 h60
  text "4.3" at 12664.84,6910 h60
  text "9" at 9815.58,6790 h60
  text "Bottom Layer" at 10225.49,6790 h60
  text "Copper" at 11155.23,6790 h60
  text "1.38mil" at 12015,6790 h60
  text "10" at 9815.58,6670 h60
  text "Bottom Solder" at 10225.49,6670 h60
  text "Solder Resist" at 11155.23,6670 h60
  text "0.40mil" at 12015,6670 h60
  text "4.3" at 12664.84,6670 h60
  text "11" at 9815.58,6550 h60
  text "Bottom Overlay" at 10225.49,6550 h60
M13 Component Bodies Top:
  text ".Layer_Name" at 577,-858.49 h60
M14 Component Bodies Bottom:
  text ".Layer_Name" at 577,-858.49 h60
M15 Courtyards Top:
  text ".Layer_Name" at 577,-858.49 h60
M16 Courtyards Bottom:
  text ".Layer_Name" at 577,-858.49 h60
Drill Drawing:
  drawing of 155 lines, arcs and shapes, not listed
  text "Symbol" at 7945.7,4057.85 h72
  text "Quantity" at 8246.36,4057.85 h72
  text "Finished Hole Size" at 8578.52,4057.85 h72
  text "Plated" at 9215,4057.85 h72
  text "Hole Type" at 9474.2,4057.85 h72
  text "Drill Layer Pair" at 9849.44,4057.85 h72
  text "15" at 8246.36,3933.35 h60
  text "7.87mil (0.200mm)" at 8578.52,3933.35 h60
  text "PTH" at 9215,3933.35 h60
  text "Round" at 9474.2,3933.35 h60
  text "Top Layer - Bottom Layer" at 9849.44,3933.35 h60
  text "295" at 8246.36,3808.85 h60
  text "12.00mil (0.305mm)" at 8578.52,3808.85 h60
  text "PTH" at 9215,3808.85 h60
  text "Round" at 9474.2,3808.85 h60
  text "Top Layer - Bottom Layer" at 9849.44,3808.85 h60
  text "8" at 8246.36,3684.35 h60
  text "17.72mil (0.450mm)" at 8578.52,3684.35 h60
  text "PTH" at 9215,3684.35 h60
  text "Round" at 9474.2,3684.35 h60
  text "Top Layer - Bottom Layer" at 9849.44,3684.35 h60
  text "5" at 8246.36,3559.85 h60
  text "20.00mil (0.508mm)" at 8578.52,3559.85 h60
  text "PTH" at 9215,3559.85 h60
  text "Round" at 9474.2,3559.85 h60
  text "Top Layer - Bottom Layer" at 9849.44,3559.85 h60
  text "78" at 8246.36,3435.35 h60
  text "35.04mil (0.890mm)" at 8578.52,3435.35 h60
  text "PTH" at 9215,3435.35 h60
  text "Round" at 9474.2,3435.35 h60
  text "Top Layer - Bottom Layer" at 9849.44,3435.35 h60
  text "24" at 8246.36,3310.85 h60
  text "38.00mil (0.965mm)" at 8578.52,3310.85 h60
  text "PTH" at 9215,3310.85 h60
  text "Round" at 9474.2,3310.85 h60
  text "Top Layer - Bottom Layer" at 9849.44,3310.85 h60
  text "31" at 8246.36,3186.35 h60
  text "40.00mil (1.016mm)" at 8578.52,3186.35 h60
  text "PTH" at 9215,3186.35 h60
  text "Round" at 9474.2,3186.35 h60
  text "Top Layer - Bottom Layer" at 9849.44,3186.35 h60
  text "32" at 8246.36,3061.85 h60
  text "40.94mil (1.040mm)" at 8578.52,3061.85 h60
  text "PTH" at 9215,3061.85 h60
  text "Round" at 9474.2,3061.85 h60
  text "Top Layer - Bottom Layer" at 9849.44,3061.85 h60
  text "4" at 8246.36,2937.35 h60
  text "44.00mil (1.118mm)" at 8578.52,2937.35 h60
  text "PTH" at 9215,2937.35 h60
  text "Round" at 9474.2,2937.35 h60
  text "Top Layer - Bottom Layer" at 9849.44,2937.35 h60
  text "30" at 8246.36,2812.85 h60
  text "49.37mil (1.254mm)" at 8578.52,2812.85 h60
  text "PTH" at 9215,2812.85 h60
  text "Round" at 9474.2,2812.85 h60
  text "Top Layer - Bottom Layer" at 9849.44,2812.85 h60
  text "A" at 7920.39,2802.86 h55.33
  text "2" at 8246.36,2688.35 h60
  text "63.00mil (1.600mm)" at 8578.52,2688.35 h60
  text "PTH" at 9215,2688.35 h60
  text "Round" at 9474.2,2688.35 h60
  text "Top Layer - Bottom Layer" at 9849.44,2688.35 h60
  text "40" at 8246.36,2563.85 h60
  text "80.71mil (2.050mm)" at 8578.52,2563.85 h60
  text "PTH" at 9215,2563.85 h60
  text "Round" at 9474.2,2563.85 h60
  text "Top Layer - Bottom Layer" at 9849.44,2563.85 h60
  text "2" at 8246.36,2439.35 h60
  text "125.00mil (3.175mm)" at 8578.52,2439.35 h60
  text "PTH" at 9215,2439.35 h60
  text "Round" at 9474.2,2439.35 h60
  text "Top Layer - Bottom Layer" at 9849.44,2439.35 h60
  text "6" at 8246.36,2314.85 h60
  text "125.98mil (3.200mm)" at 8578.52,2314.85 h60
  text "PTH" at 9215,2314.85 h60
  text "Round" at 9474.2,2314.85 h60
  text "Top Layer - Bottom Layer" at 9849.44,2314.85 h60
  text "572 Total" at 8246.36,2190.35 h60
  text "FOR 7.87MIL DRILL +0/-7.87MIL" at 7878,1972 h60
  text "FOR 12MIL DRILL +0/-12MIL" at 7878,1852 h60
  text "FOR PTH DRILL +/-3MIL" at 7878,1752 h60
  text ".Layer_Name" at 577,-858.49 h60
M17 Embedded Cavity:
  text ".Layer_Name" at 577,-858.49 h60
M18 Embedded Assembly:
  text ".Layer_Name" at 577,-858.49 h60
M19 Embedded Keepout:
  text ".Layer_Name" at 577,-858.49 h60

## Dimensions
0,0 to 7480.31,0 on M2 Board Dimensions
0,-400 to 1000,-400 on M2 Board Dimensions
0,0 to 0,4133.86 on M2 Board Dimensions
